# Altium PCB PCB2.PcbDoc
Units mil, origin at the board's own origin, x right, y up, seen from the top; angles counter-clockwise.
Board outline 1545.03 x 1900.03 mil, 2 copper layers (Top Layer, Bottom Layer); 45 components, 45 nets, 176 pads, 0 vias.
Unrouted connection lines stored in the file: 10.
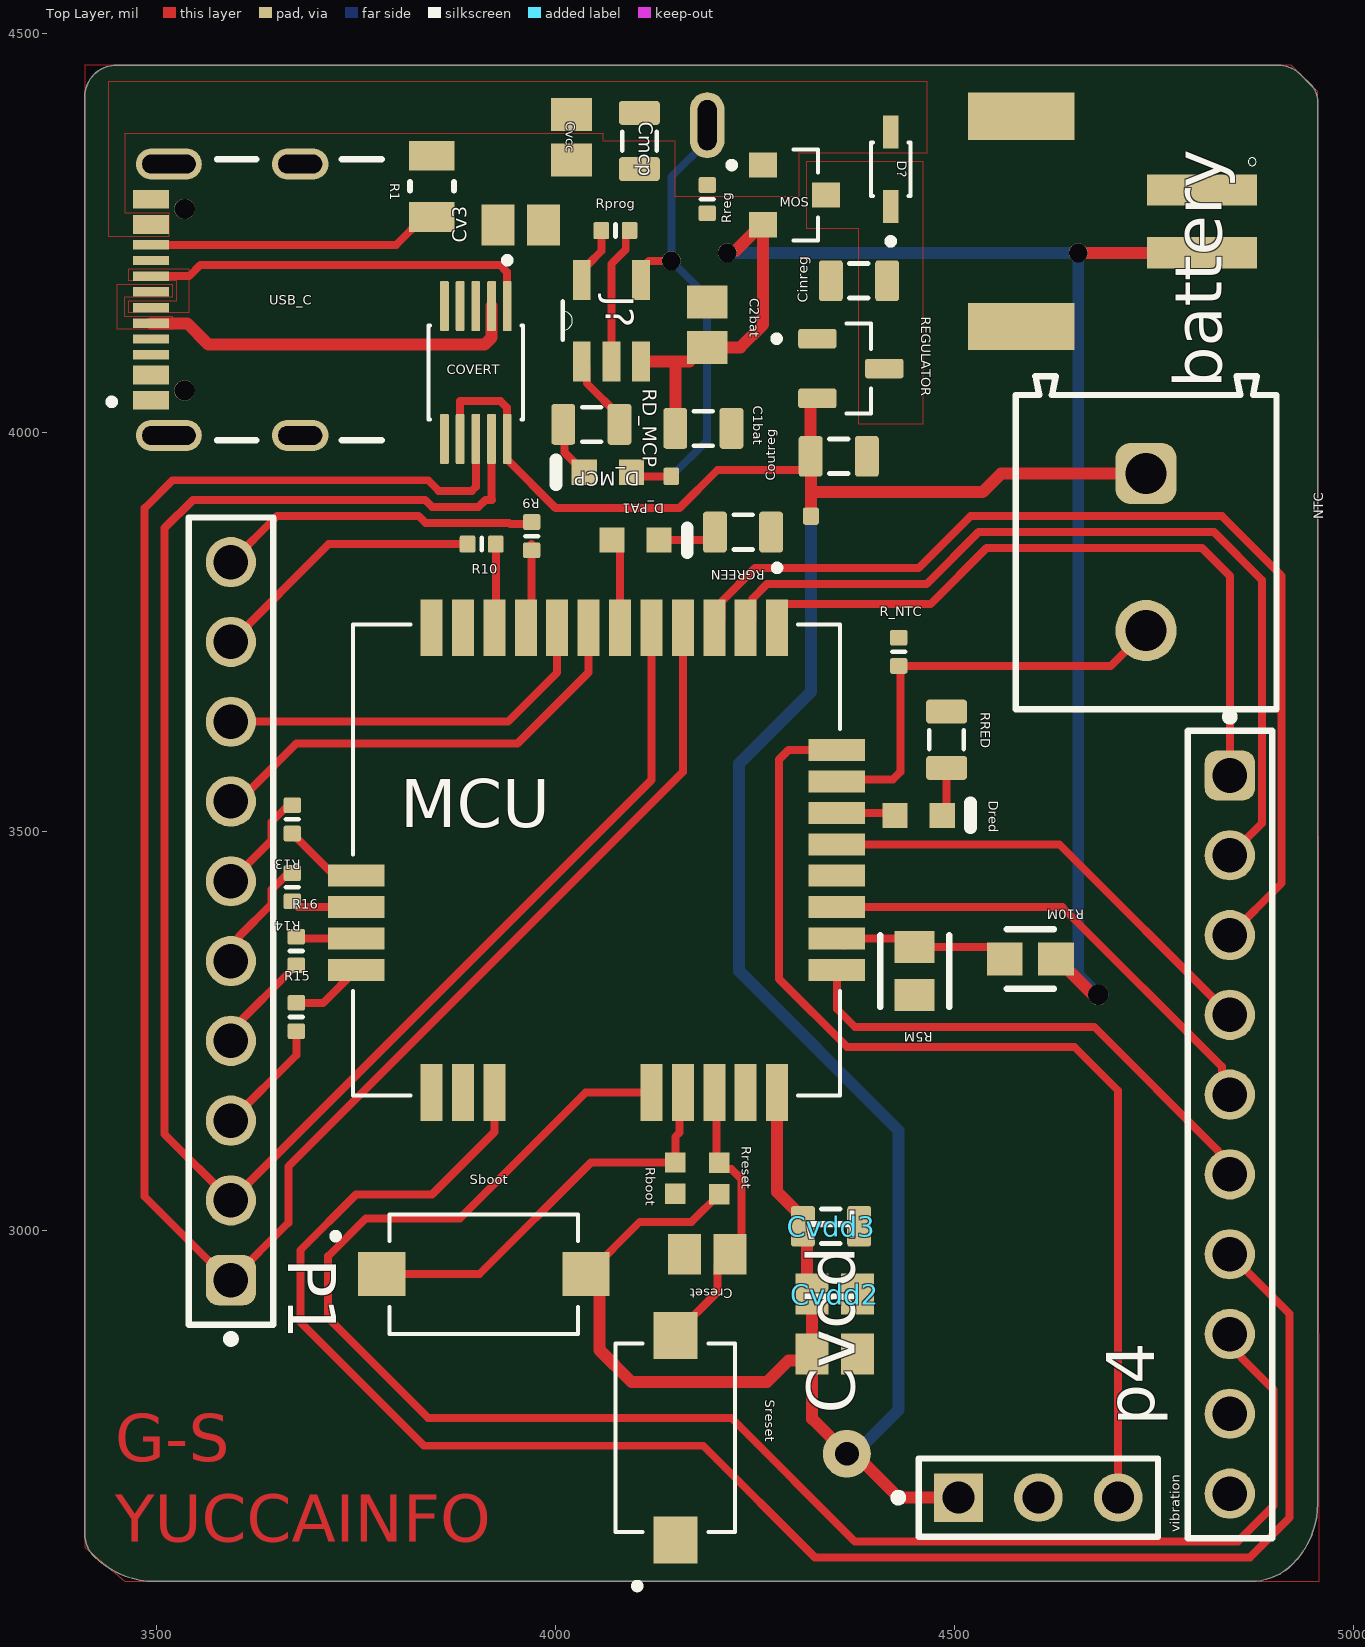
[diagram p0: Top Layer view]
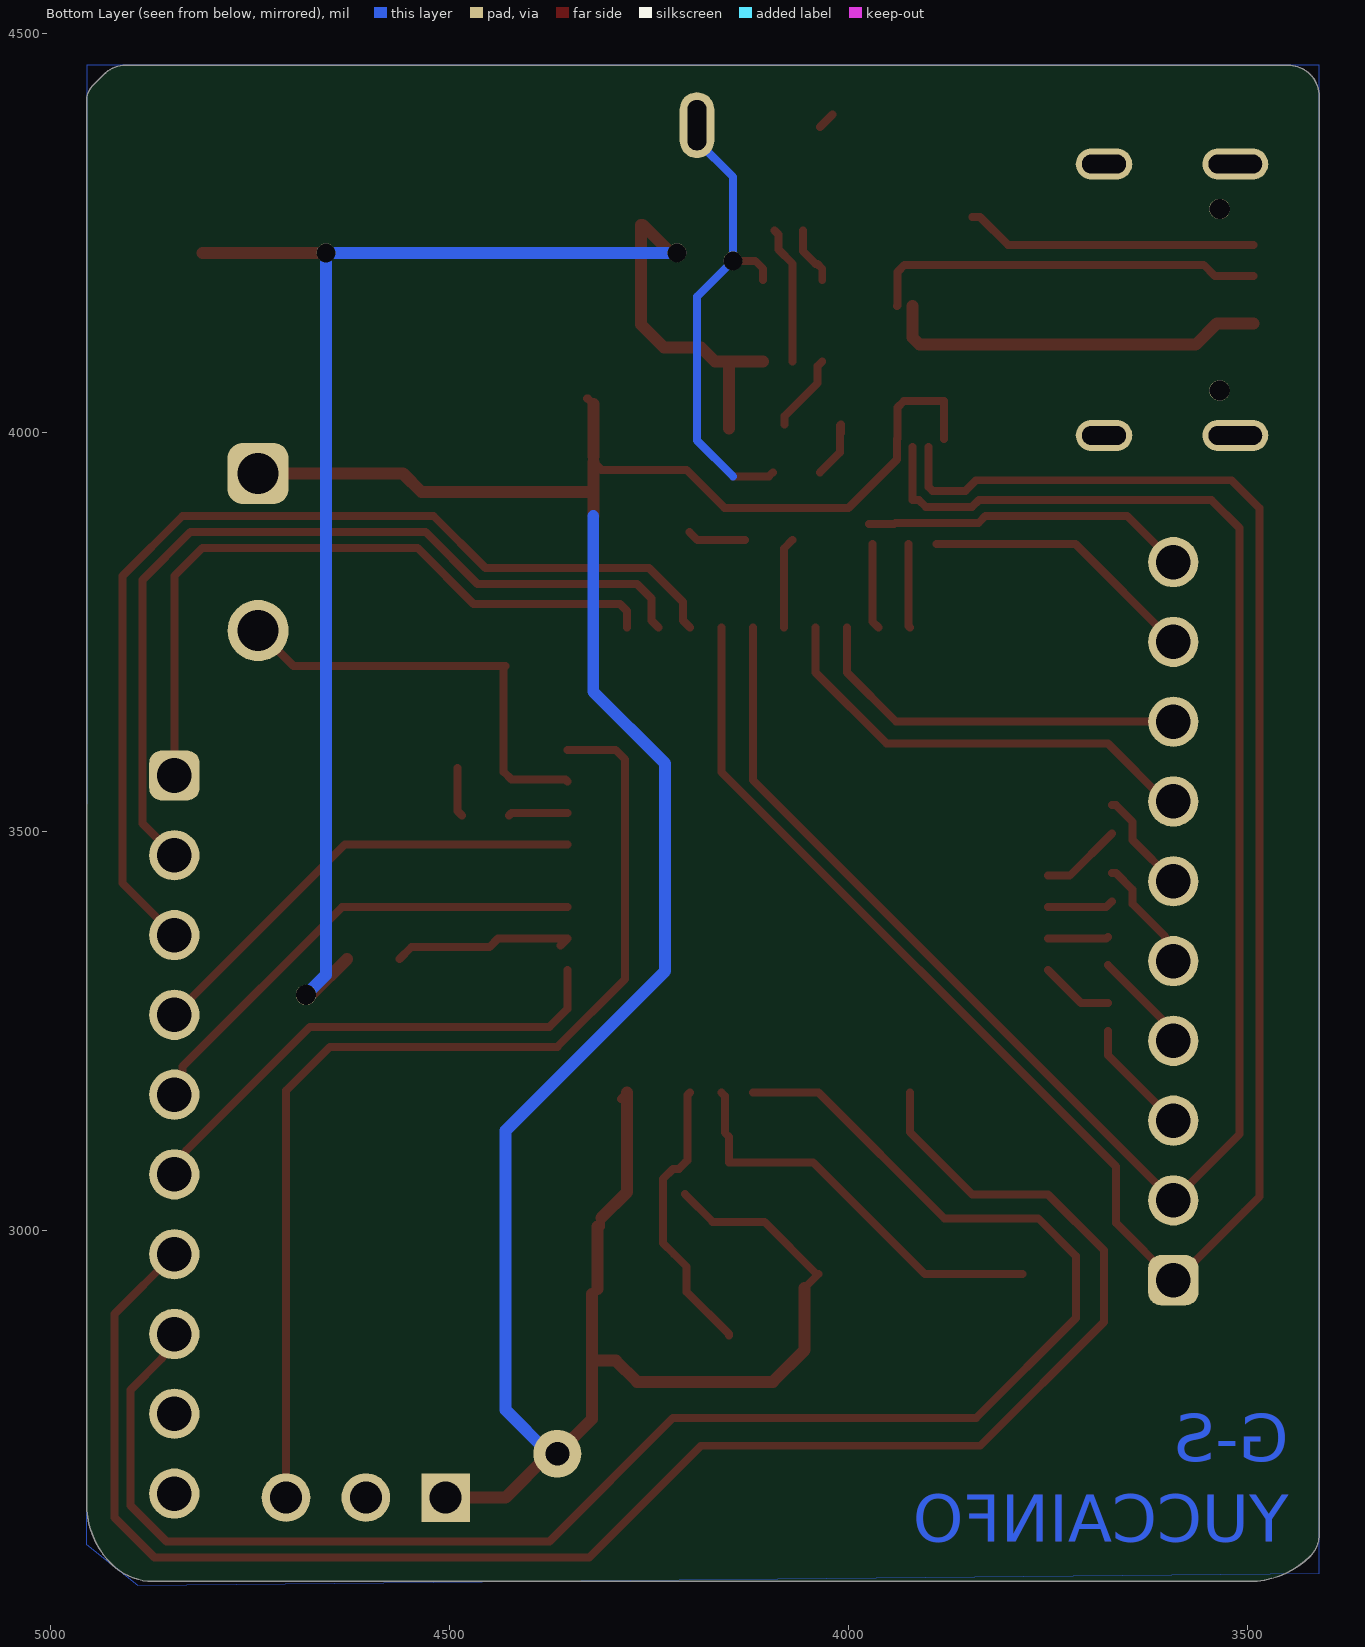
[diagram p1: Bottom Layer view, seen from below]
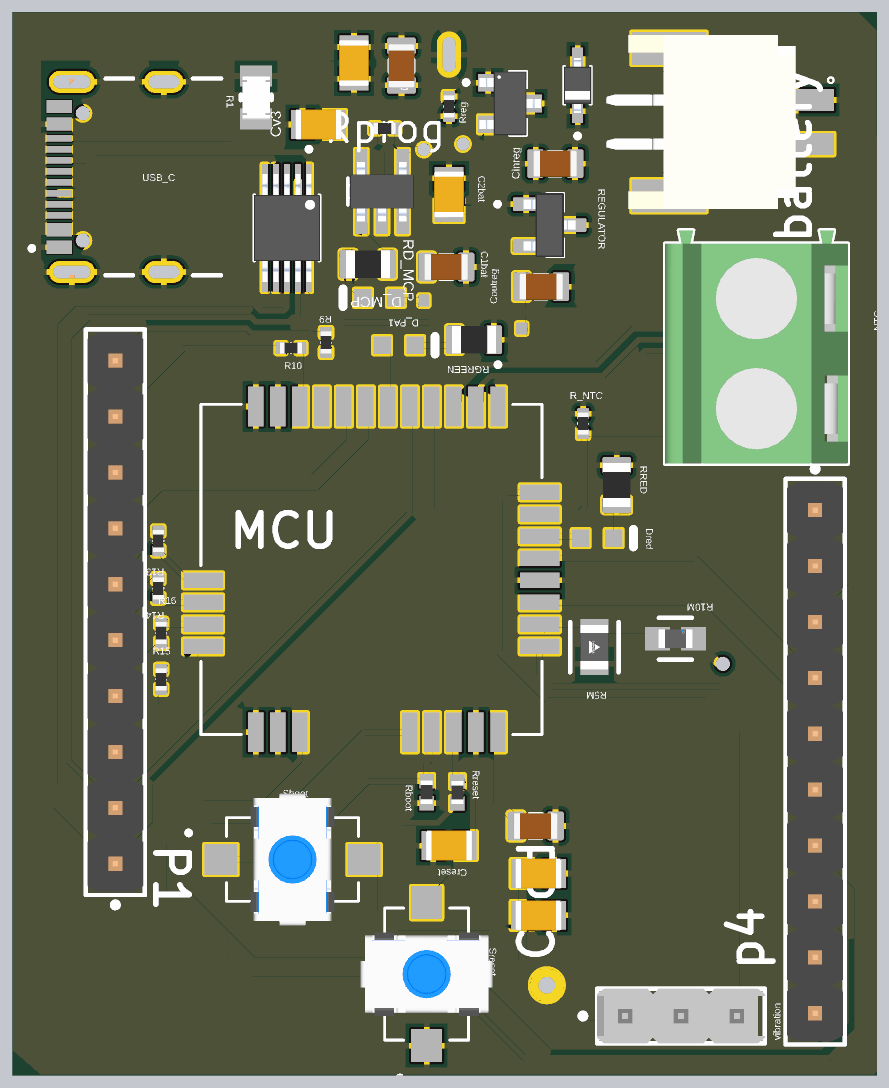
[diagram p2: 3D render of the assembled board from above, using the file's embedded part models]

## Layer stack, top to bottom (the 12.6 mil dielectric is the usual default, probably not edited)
Top Solder: solder mask 0.4, Solder Resist, Dk 3.5
Top Layer: signal copper 1.4
Dielectric 1: dielectric 12.6, FR-4, Dk 4.8
Bottom Layer: signal copper 1.4
Bottom Solder: solder mask 0.4, Solder Resist, Dk 3.5

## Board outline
3409.99,2619.14 3409.99,4420.86 cw(c3449.14,4420.86) 3421.45,4448.55 cw(c3449.14,4420.86) 3449.14,4460.02 4905.86,4460.02 cw(c4905.86,4420.86) 4933.55,4448.55 4946.48,4435.62 cw(c4925.86,4415) 4955.02,4415 4955.02,2657.43 cw(c4847.57,2657.43) 4923.55,2581.45 cw(c4871.72,2633.28) 4871.72,2559.99 3497.43,2559.99 cw(c3497.43,2667.43) 3421.45,2591.45 cw(c3449.14,2619.14)

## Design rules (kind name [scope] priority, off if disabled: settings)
Clearance [All] p1 off: gap=10 ignorepadtopadclearanceinfootprint=FALSE
DiffPairsRouting [All] p1: maxlimit=10 minlimit=10 mostfreqgap=10 toplayer_minwidth=15 toplayer_maxwidth=15 toplayer_prefwidth=15 bottomlayer_minwidth=15 bottomlayer_maxwidth=15 bottomlayer_prefwidth=15 maxuncoupledlength=500
PolygonConnect [All] p1: connectstyle=Relief reliefconductorwidth=10 reliefentries=4 polygonreliefangle="90 Angle" airgapwidth=10
RoutingVias [All] p1: holewidth=28 width=50 viastyle="Through Hole" minholewidth=28 minwidth=50 maxholewidth=28 maxwidth=50
SolderMaskExpansion [All] p1: expansion=4 istentingtop=FALSE
SupplyNets "Schematic Supply Nets_3" [InNet('GND')] p1: voltage=0.000
SupplyNets "Schematic Supply Nets_2" [InNet('Vbat')] p2: voltage=0.000
SupplyNets "Schematic Supply Nets_1" [InNet('VBUS')] p3: voltage=0.000
SupplyNets "Schematic Supply Nets" [InNet('3V3')] p4: voltage=0.000
Width [All] p1: maxlimit=10 minlimit=10 preferedwidth=10
29 further rules are at their usual default settings.

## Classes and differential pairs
differential pair D: +D_P -D_N

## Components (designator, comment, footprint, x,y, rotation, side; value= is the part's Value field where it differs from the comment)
battery "" JST_S2B-PH-SM4-TB 4810,4264.37 r90 top
C1bat "Capacitor 4.7µF +/-40% 25V 0805" CAPC0805(2012)145_L 4185,4005 r180 top value=4.7µF
C2bat "Capacitor 100 nF +/-10% 50 V 0805" CAPC2013X95X50LL10T25 4190,4135 r270 top value=100nF
Cinreg "Capacitor 10µF +/-20% 25V 0805" CAPC0805(2012)145_L 4380,4190 r180 top value=10µF
Cmcp "Capacitor 4.7µF +/-40% 25V 0805" CAPC0805(2012)145_L 4105,4365 r270 top value=4.7µF
Coutreg "Capacitor 10µF +/-20% 25V 0805" CAPC0805(2012)145_L 4355,3970 r0 top value=10µF
COVERT "COM-16278" SOP50P490X120-10N 3900,4075 r270 top
Creset "Capacitor 100 nF +/-10% 50 V 0805" CAPC2013X95X50LL10T25 4190,2970 r180 top value=100nF
Cv3 "Capacitor 100 nF +/-10% 50 V 0805" CAPC2013X95X50LL10T25 3956.46,4260 r180 top value=100nF
Cvcc "Capacitor 100 nF +/-10% 50 V 0805" CAPC2013X95X50LL10T25 4020,4370 r270 top value=100nF
Cvdd1 "Capacitor 100 nF +/-10% 50 V 0805" CAPC2013X95X50LL10T25 4350,2845 r180 top value=100nF
Cvdd2 "Capacitor 100 nF +/-10% 50 V 0805" CAPC2013X95X50LL10T25 4350,2920 r180 top value=100nF
Cvdd3 "Capacitor 10µF +/-20% 25V 0805" CAPC0805(2012)145_L 4345,3005 r180 top value=10µF
D? "B5819WS-TP" SOD2512X115N 4420,4330 r90 top
D_MCP "" LTST-C190GKT_V 4065.47,3950 r180 top
D_PA1 "" AVAG-HSMX-C190_V 4100,3865 r0 top
Dred "" AVAG-HSMX-C190_V 4455,3520 r0 top
J? "MCP73831T-2ACI/OT" SOT95P280X145-5N 4070,4140 r90 top
MCU "RAK3172" XCVR_RAK3172-8-SM-NI 4051.18,3464.06 r0 top
MOS "" TRANS_TSM500P02CX 4299.37,4297.6 r0 top
NTC "" 691213710002 4740,3850 r270 top
P1 "" 61301011121 3593.06,3387.44 r90 top
p4 "" 61301011121 4845,3120 r270 top
R1 "CRCW08055K10FKEA" FP-CRCW0805-e3-MFG 3845,4308.39 r270 top
R5M "" FP-WSLP0805-MFG 4450,3324.92 r90 top
R9 "Resistor 22R  +/-5 % 0402 63 mW" RESC0402(1005)_L 3970,3870 r90 top value=22
R10 "Resistor 22R  +/-5 % 0402 63 mW" RESC0402(1005)_L 3907.28,3860 r180 top value=22
R10M "" FP-CRCW0603-e3-IPC_A 4595,3340 r0 top
R13 "Resistor 22R  +/-5 % 0402 63 mW" RESC0402(1005)_L 3670,3515 r270 top value=22
R14 "Resistor 22R  +/-5 % 0402 63 mW" RESC0402(1005)_L 3670,3430 r270 top value=22
R15 "Resistor 22R  +/-5 % 0402 63 mW" RESC0402(1005)_L 3675,3267.28 r90 top value=22
R16 "Resistor 22R  +/-5 % 0402 63 mW" RESC0402(1005)_L 3675,3350 r90 top value=22
R_NTC "10KR2F" RESC0402(1005)_L 4430,3725 r270 top value=10k
Rboot "Resistor 10k +/-1% 0402 63 mW" RESC1005X40X25ML05T05 4150,3065.31 r90 top value=10k
RD_MCP "Resistor 470R +/-5% 0805 125 mW" RESC0805(2012)_L 4045,4010 r0 top value=470
REGULATOR "" SOT95P237X112-3N 4370,4080 r0 top
RGREEN "1KR5J" RESC0805(2012)_L 4235,3875 r0 top value=1k
Rprog "2KR2J" RESC0402(1005)_L 4075,4252.91 r0 top value=2k
RRED "1KR5J" RESC0805(2012)_L 4490,3615 r90 top value=1k
Rreg "10KR2F" RESC0402(1005)_L 4190,4292.28 r90 top value=10k
Rreset "Resistor 10k +/-1% 0402 63 mW" RESC1005X40X25ML05T05 4205,3065 r270 top value=10k
Sboot "" SW_TS10-63-26-BE-250-SMT-TR 3910,2945 r0 top
Sreset "" SW_TS10-63-26-BE-250-SMT-TR 4150,2740 r90 top
USB_C "USB4105-GF-A" GCT_USB4105-GF-A 3679.88,4166.22 r90 top
vibration "" MOLX-22-28-4033_V 4605,2665 r0 top

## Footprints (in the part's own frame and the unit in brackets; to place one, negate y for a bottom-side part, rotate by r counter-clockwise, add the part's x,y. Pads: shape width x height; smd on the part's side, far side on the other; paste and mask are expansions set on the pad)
61301011121 [mm] "Pin Header, pitch 2.54 mm, THT, Vertical, single row, 10p"
  rrect50% 1.6x1.6 hole 1.1: 1(-11.43,0)
  round 1.6 hole 1.1: 2(-8.89,0) 3(-6.35,0) 4(-3.81,0) 5(-1.27,0) 6(1.27,0) 7(3.81,0) 8(6.35,0) 9(8.89,0) 10(11.43,0)
  silkscreen extent -13.42,-1.35 12.85,1.35, body extent -12.7,-1.27 12.7,1.27, height 8.57
691213710002 [mm] "5,00mm - modular - green - Horizontal entry with rising cage clamp -  10,0mm height - 02p"
  rrect50% 1.95x1.95 hole 1.3: 1(-2.5,0)
  round 1.95 hole 1.3: 2(2.5,0)
  silkscreen extent -5.6,-4.15 5,4.15, body extent -5.6,-4.15 5,4.15, height 10.05
AVAG-HSMX-C190_V [mm] "SMD, 2-Leads, Body 1.6x0.8mm, Height 0.9mm"
  rect 0.8x0.8 smd: 1(-0.75,0) 2(0.75,0)
  silkscreen extent 1.65,-0.4 1.65,0.4, body extent -0.8,-0.4 0.8,0.4, height 0.9
CAPC0805(2012)145_L [mm] "Chip Capacitor, Body 2.0x1.2mm, Height 1.45mm, IPC High Density"
  rrect25% 0.76x1.3 smd: 1(-0.9,0) 2(0.89,0)
  silkscreen extent -0.3,-0.55 0.3,0.55, body extent -1,-0.6 1,0.6, height 1.45
CAPC2013X95X50LL10T25 [mm] "Chip Capacitor, 2-Leads, Body 2.10x1.35mm, IPC High Density"
  rect 1.05x1.3 smd: 1(-0.725,0) 2(0.725,0)
  body extent -1.05,-0.67 1.05,0.67, height 0.95
FP-CRCW0603-e3-IPC_A [mil]
  rect 44.69x41.82 smd paste+0 mask+0: 1(-32.1,0) 2(32.1,0)
  silkscreen extent -30,-37 30,37, body extent -74,-41 74,41, height 10
FP-CRCW0805-e3-MFG [mm]
  rect 0.95x1.45 smd paste+0 mask+0: 1(-0.975,0) 2(0.975,0)
  silkscreen extent -0.13,-0.7 0.13,0.7, body extent -1.55,-0.82 1.55,0.82, height 0.25
FP-WSLP0805-MFG [mm]
  rect 1.02x1.27 smd paste+0 mask+0: 1(-0.76,0) 2(0.76,0)
  silkscreen extent -1.14,-1.1 1.14,1.1, body extent -1.37,-0.86 1.37,0.86, height 0.25
GCT_USB4105-GF-A [mm]
  rect 0.6x1.15 smd mask+0.05: A1_B12(-3.2,4.755) A4_B9(-2.4,4.755) B1_A12(3.2,4.755) B4_A9(2.4,4.755)
  rect 0.3x1.15 smd mask+0.05: A5(-1.25,4.755) A6(-0.25,4.755) A7(0.25,4.755) A8(1.25,4.755) B5(1.75,4.755) B6(0.75,4.755) B7(-0.75,4.755) B8(-1.75,4.755)
  oval 1x2.1 hole 0.6 slot 1.7 at 90 deg: SH1(-4.32,4.18) SH2(4.32,4.18)
  oval 1x1.8 hole 0.6 slot 1.4 at 90 deg: SH3(-4.32,0) SH4(4.32,0)
  round 0.65 hole 0.65 unplated: ""(-2.89,3.68) ""(2.89,3.68)
  silkscreen extent -4.47,-2.6 4.47,6.1
JST_S2B-PH-SM4-TB [mm]
  rect 1x3.5 smd: 1(1,0) 2(-1,0)
  rect 1.5x3.4 smd: P1(3.35,5.75) P2(-3.35,5.75)
  silkscreen extent 1.77,-1.73 2.03,-1.47, body extent -3.95,0 3.95,8.6, height 5.5
LTST-C190GKT_V [mm] "SMD, 2-Leads, Body 1.6x0.8mm"
  rect 0.8x0.8 smd: 1(-0.75,0) 2(0.75,0)
  silkscreen extent 1.65,-0.4 1.65,0.4, body extent -0.8,-0.4 0.8,0.4, height 0.9
MOLX-22-28-4033_V [mm] "THD, 3-Leads, Body 7.62x2.49mm, Pitch 2.54mm"
  rect 1.55x1.55 hole 1.02: 1(-2.54,0)
  round 1.55 hole 1.02: 2(0,0) 3(2.54,0)
  silkscreen extent -4.58,-1.24 3.81,1.24, body extent -3.81,-1.24 3.81,1.24, height 8.38
RESC0402(1005)_L [mm] "Chip Resistor, Body 1.0x0.5mm, IPC High Density"
  rrect25% 0.5x0.55 smd: 1(-0.45,0) 2(0.45,0)
  silkscreen extent 0,-0.2 0,0.2, body extent -0.5,-0.25 0.5,0.25, height 0.3
RESC0805(2012)_L [mm] "Chip Resistor, Body 2.0x1.3mm, IPC High Density"
  rrect25% 0.76x1.3 smd: 1(-0.9,0) 2(0.89,0)
  silkscreen extent -0.3,-0.55 0.3,0.55, body extent -1,-0.62 1,0.63, height 0.6
RESC1005X40X25ML05T05 [mm] "Chip Resistor, 2-Leads, Body 1.05x0.55mm, IPC Low Density"
  rect 0.65x0.65 smd: 1(-0.5,0) 2(0.5,0)
  body extent -0.53,-0.28 0.53,0.28, height 0.4
SOD2512X115N [mm]
  rect 1.05x0.5 smd: A(1.185,0) C(-1.185,0)
  silkscreen extent -2.4,-0.63 0.85,0.63, body extent -1.25,-0.63 1.25,0.63, height 1.15
SOP50P490X120-10N [mm]
  rrect25% 1.59x0.28 smd: 1(-2.115,1) 2(-2.115,0.5) 3(-2.115,0) 4(-2.115,-0.5) 5(-2.115,-1) 6(2.115,-1) 7(2.115,-0.5) 8(2.115,0) 9(2.115,0.5) 10(2.115,1)
  silkscreen extent -3.68,-1.5 1.5,1.5, body extent -2.45,-1.5 2.45,1.5, height 1
SOT95P237X112-3N [mm]
  rrect25% 1.22x0.62 smd: 1(-1.065,0.95) 2(-1.065,-0.95) 3(1.065,0)
  silkscreen extent -2.46,-1.43 0.64,1.43, body extent -1.18,-1.45 1.18,1.45, height 1.12
SOT95P280X145-5N [mil]
  rect 50x22 smd: 1(-51,37) 2(-51,0) 3(-51,-37) 4(51,-37) 5(51,37)
  silkscreen extent -24,49 24,61, body extent -53,-57 53,57, height 57
SW_TS10-63-26-BE-250-SMT-TR [mm]
  rect 1.5x1.4 smd: 1(-3.25,0) 2(3.25,0)
  silkscreen extent -4.82,-1.9 3,1.9, body extent -1.9,-3.7 1.9,3.7, height 2.2
TRANS_TSM500P02CX [mm]
  rect 0.9x0.8 smd: 1(-1,0.95) 2(-1,-0.95) 3(1,0)
  silkscreen extent -2.1,-1.45 0.75,1.45, body extent -1.4,-1.45 1.4,1.45, height 1.2
XCVR_RAK3172-8-SM-NI [mm]
  rect 0.7x1.8 smd: 1(5.75,7.4) 2(4.75,7.4) 3(3.75,7.4) 4(2.75,7.4) 5(1.75,7.4) 6(0.75,7.4) 7(-0.25,7.4) 8(-1.25,7.4) 9(-2.25,7.4) 10(-3.25,7.4) 11(-4.25,7.4) 12(-5.25,7.4) 17(-5.25,-7.4) 18(-4.25,-7.4) 19(-3.25,-7.4) 20(1.75,-7.4) 21(2.75,-7.4) 22(3.75,-7.4) 23(4.75,-7.4) 24(5.75,-7.4)
  rect 1.8x0.7 smd: 13(-7.65,-0.5) 14(-7.65,-1.5) 15(-7.65,-2.5) 16(-7.65,-3.5) 25(7.65,-3.5) 26(7.65,-2.5) 27(7.65,-1.5) 28(7.65,-0.5) 29(7.65,0.5) 30(7.65,1.5) 31(7.65,2.5) 32(7.65,3.5)
  silkscreen extent -7.75,-7.5 7.75,9.4

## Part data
battery: library part S2B-PH-SM4-TB, "Connector Header Surface Mount, Right Angle 2 position 0.079 (2.00mm)", Package=None
C1bat Cmcp: library part CMP-001-00080-4, "Chip Capacitor, 4.7µF +/-40%, 25V, 0805, Thickness 1.45 mm", Case/Package=0805, Max Operating Temperature=85°C, Min Operating Temperature=-55°C, Tolerance=20%, Voltage Rating=25V
C2bat Creset Cv3 Cvcc Cvdd1 Cvdd2: library part CMP-001-00018-6, "Chip Capacitor, 100 nF, +/- 10%, 50 V, 0805 (2012 Metric)", Capacitor Type=Ceramic, Case/Package=0805, Max Operating Temperature=125°C, Min Operating Temperature=-55°C, Tolerance=10%, Voltage Rating=50V
Cinreg Coutreg Cvdd3: library part CMP-001-00079-4, "Chip Capacitor, 10µF +/-20%, 25V, 0805, Thickness 1.45 mm", Case/Package=0805, Max Operating Temperature=85°C, Min Operating Temperature=-55°C, Tolerance=10%, Voltage Rating=25V
COVERT: "SparkFun Accessories USB to Serial IC - CH340E (10 Pack)", Package=None
D?: "Diode Schottky 40 V 1A Surface Mount SOD-323", Package="SOD-323 Taiwan Semiconductor Corporation"
D_MCP: library part CMP-007-00022-2, "LED Uni-Color Green, 100 mW, 30 mA, -55 to 85 degC, 2-Pin SMD, RoHS, Tape and Reel", Case/Package=0603, Colour=Green, Forward Current=20mA, Forward Voltage=2.1V, Manufacturer=Lite-On, Max Operating Temperature=85°C, Min Operating Temperature=-55°C, Package Description="2-Pin Surface Mount Device, Body 1.6 x 0.8 mm", Package Quantity=3000, Package Reference=C190GKT, Power=100mW
D_PA1: library part CMP-007-00017-2, "LED Uni-Color Yellow, 65 mW, 20 mA, -40 to 85 degC, 2-Pin SMD, RoHS, Tape and Reel", Case/Package=0603, Colour=Yellow, Forward Current=20mA, Forward Voltage=2.1V, Manufacturer=Avago, Max Operating Temperature=85°C, Min Operating Temperature=-40°C, Package Description="2-Pin Surface Mount Device, Body 1.6 x 0.8 mm, Height 0.9 mm", Package Quantity=4000, Package Reference=HSMX-C190, Power=52mW
Dred: library part CMP-007-00014-2, "LED Uni-Color Red, 65 mW, 20 mA, -40 to 85 degC, 2-Pin SMD, RoHS, Tape and Reel", Case/Package=0603, Colour=Red, Forward Current=20mA, Forward Voltage=1.8V, Manufacturer=Avago, Max Operating Temperature=85°C, Min Operating Temperature=-40°C, Package Description="2-Pin Surface Mount Device, Body 1.6 x 0.8 mm, Height 0.9 mm", Package Quantity=4000, Package Reference=HSMX-C190, Power=78mW
J?: "Charger IC Lithium Ion/Polymer SOT-23-5", Package="SOT-23 Microchip"
MCU: library part RAK3172-8-SM-NI, "RF IC Transceiver LoRaWAN 864MHz, 865MHz, 868MHz 2V ~ 3.6V Supply, Without IPEX Connector", Package=None
MOS: library part TSM500P02CX, "P-Channel 20 V 4.7A (Tc) 1.56W (Tc) Surface Mount SOT-23", Package="SOT-23-3 Taiwan Semiconductor"
NTC: library part CMP-1502-02526-2, Color=Green, Current=10A, Max Operating Temperature=105°C, Min Operating Temperature=-40°C, Voltage=300V
P1 p4: library part CMP-1502-01082-5, Color=Black, Contact Resistance=20mΩ, Current Rating=3A, Flammability Rating="UL94 V-0", Insulation Resistance=1GΩ, Max Operating Temperature=105°C, Min Operating Temperature=-40°C, Operating Supply Voltage=250V
R1: library part CMP-2001-04024-2, "RES Thick Film, 5.1kΩ, 1%, 0.125W, 100ppm/°C, 0805", Case Code (Imperial)=0805, Case Code (Metric)=2012, Max Operating Temperature=155°C, Max Power Dissipation=125mW, Min Operating Temperature=-55°C, Package Quantity=10, Resistance=5.1kR, Temperature Coefficient=100ppm/°C, Tolerance=1%, Voltage Rating=150V
R5M: library part CMP-02407-013125-1, "RES 0.005 OHM 1% 1W 0805", Case Code (Imperial)=0805, Case Code (Metric)=2012, Max Operating Temperature=170°C, Max Power Dissipation=1W, Min Operating Temperature=-65°C, Resistance=5mR, Resistance Tolerance=1%, Resistor Type="Metal Strip", Temperature Coefficient=110ppm/°C
R9 R10 R13 R14 R15 R16: library part CMP-009-00164-3, "Chip Resistor, 22 Ohms, +/-5 %, 63 mW, -55 to 155 degC, 0402", Case/Package=0402, Max Operating Temperature=155°C, Min Operating Temperature=-55°C, Power=63mW, Tolerance=5%
R10M: library part CMP-2000-03844-2, "RES Thick Film, 10MΩ, 5%, 0.1W, 200ppm/°C, 0603", Case Code (Imperial)=0603, Case Code (Metric)=1608, Max Operating Temperature=155°C, Max Power Dissipation=100mW, Min Operating Temperature=-55°C, Package Quantity=1, Resistance=10MR, Temperature Coefficient=200ppm/°C, Tolerance=5%, Voltage Rating=75V
R_NTC Rreg: library part CMP-009-00066-2, "10K 0.063W 1% 0402 (1005 Metric)  SMD", Case/Package=0402, Power=63mW, Tolerance=1%
Rboot Rreset: library part CMP-009-00019-5, "Chip Resistor, 10 KOhm, +/- 1%, 63 mW, -55 to 155 degC, 0402 (1005 Metric)", Case/Package=0402, Max Operating Temperature=155°C, Min Operating Temperature=-55°C, Power=63mW, Tolerance=1%, Voltage Rating=50V
RD_MCP: library part CMP-009-00122-3, "Chip Resistor, 470 Ohms, +/-5%, 125 mW, -55 to 155 degC, 0805", Case/Package=0805, Max Operating Temperature=155°C, Min Operating Temperature=-55°C, Power=125mW, Tolerance=5%
REGULATOR: library part MCP1700T-3302E_TT, "Pwr Sply Func,Voltage Regulator,LDO,SOT-23,PD 369.6mW,VO 3.3V,Regline +/-0.75%/V", Package="SOT-23 Microchip"
RGREEN RRED: library part CMP-009-00076-2, "1K 0.125W 5% 0805 (2012 Metric)  SMD", Case/Package=0805, Power=125mW, Tolerance=5%
Rprog: library part CMP-009-00091-2, "2K 0.063W 5% 0402 (1005 Metric)  SMD", Case/Package=0402, Power=63mW, Tolerance=5%
Sboot Sreset: library part TS10-63-26-BE-250-SMT-TR, "6.1 x 3.8 mm, 2.6 mm Actuator Height, 250 gf, Surface Mount, SPST, Tactile Switch", Package=None
USB_C: Package=None
vibration: library part CMP-1676-00001-5, "Male Header, Pitch 2.54 mm, 1 x 3 Position, Height 8.38 mm, Tail Length 3.18 mm, RoHS, Bulk", Colour=Black, Current Rating="4 A", Manufacturer=Molex, Max Operating Temperature="75 degC", Min Operating Temperature="0 degC", Package Quantity=1, Voltage Rating="250 V"

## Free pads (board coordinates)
  rrect100% 43.31x82.68 hole 62.99 slot 23.62 at 0 deg paste-99999 mask+0: 4(4190,4385)
  rrect25% 19.68x21.65 smd: 5(4145,3945) 5(4320,3895)
  round 23.62 hole 23.62 unplated: 6(4145,4215) 9(4215,4225) 9(4655,4225)
  round 60 hole 30: 10(4365,2720)
  round 25.59 hole 25.59 unplated: 11(4680,3295)

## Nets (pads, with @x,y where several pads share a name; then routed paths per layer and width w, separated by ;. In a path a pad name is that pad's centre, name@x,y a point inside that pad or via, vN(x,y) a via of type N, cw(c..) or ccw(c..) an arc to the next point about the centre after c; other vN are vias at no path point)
3V3: Coutreg.1 COVERT.7 COVERT.10 Cv3.1 Cvdd1.2 Cvdd2.2 Cvdd3.2 MCU.24 NTC.1 pad.5@4320,3895 pad.10 REGULATOR.2 Rreset.2 Sboot.2 vibration.1 | length 3782.6
  Top Layer w10: COVERT.7 3880.32,4039.14 3930.86,4039.14 3938.86,4031.14 3938.86,3992.24 COVERT.10 3939.37,3965.94 4000,3905.32 4155.31,3905.32 4203.15,3953.15 4309.61,3953.15 Coutreg.1@4319.57,3963.11 ; Sboot.2@4055,2927.95 Sboot.2 4039.92,2945 4105.51,3010.59 4170.28,3010.59 Rreset.2 ; MCU.24 MCU.24@4285.43,3164.85 ; Cvdd3.2 Cvdd3.2@4309.96,3015.63 ; Cvdd1.2@4313.1,2836.65 Cvdd1.2 ; Cvdd2.2@4314.96,2926.5 Cvdd2.2 ; Coutreg.1 Coutreg.1@4319.57,3963.11 ; REGULATOR.2@4319.57,4035.39 4326.77,4042.6 REGULATOR.2 ; pad.5@4319.78,3895.22 pad.5@4320,3895 ; 4319.78,3925.22 4320,3925 ; Coutreg.1@4319.78,3962.89 Coutreg.1@4319.57,3963.11
  Top Layer w15: Sboot.2@4055,2927.95 4055,2850 4095,2810 4265,2810 4291.65,2836.65 Cvdd1.2@4313.1,2836.65 ; MCU.24 4277.56,3048.03 Cvdd3.2@4309.96,3015.63 ; Cvdd2.2@4314.96,2926.5 Cvdd3.2@4314.96,3005 ; Coutreg.1 REGULATOR.2@4319.57,4035.39 ; pad.5@4319.78,3895.22 4319.78,3925.22 Coutreg.1@4319.78,3962.89 ; 4320,3925 4535,3925 4558.43,3948.43 NTC.1 ; Cvdd2.2 Cvdd1.2 4321.46,2763.78 pad.10@4365,2720.24 ; pad.10 4375,2720 4430,2665 vibration.1
  Bottom Layer w10: pad.10 pad.10@4375,2720
  Bottom Layer w15: 4320,3895 4320,3675 4230,3585 4230,3325 4430,3125 4430,2775 pad.10@4375,2720
BOOT0: MCU.21 Rboot.2 Sboot.1 | length 517.6
  Top Layer w10: Sboot.1 3904.39,2945 4044.39,3085 Rboot.2 4150,3117.2 4155.08,3122.28 4155.08,3168.35 MCU.21
D_N: COVERT.2 USB_C.A7 USB_C.B7 | length 481.2
  Top Layer w15: USB_C.B7 3538.31,4136.69 3565,4110 3910.9,4110 3919.68,4118.79 COVERT.2
D_P: COVERT.1 USB_C.A6 USB_C.B6 | length 498.8
  Top Layer w10: USB_C.B6 3540.75,4195.75 3555,4210 3930,4210 3938.86,4201.14 3938.86,4158.78 COVERT.1
GND: battery.1 C1bat.1 C2bat.1 Cinreg.2 Cmcp.2 Coutreg.2 COVERT.3 Creset.2 Cv3.2 Cvcc.2 Cvdd1.1 Cvdd2.1 Cvdd3.1 MCU.11 MCU.12 MCU.17 MCU.18 MCU.23 MCU.28 p4.9 p4.10 pad.11 R1.1 R5M.1 R_NTC.1 Rboot.1 REGULATOR.1 RGREEN.2 RRED.2 Rreg.1 Sreset.1 USB_C.A1_B12 USB_C.B1_A12 USB_C.SH1 USB_C.SH2 USB_C.SH3 USB_C.SH4 vibration.2
I2C_SCL: P1.10 R9.2 | length 409.5
  Top Layer w10: P1.10 3651.06,3895.43 3828.24,3895.43 3836.94,3886.73 3941.4,3886.73 3943.13,3885 R9.2@3974.19,3885
I2C_SDA: P1.9 R10.2 | length 347.3
  Top Layer w10: P1.9 3715.63,3860 R10.2
LEV_BAT: MCU.26 R5M.2 R10M.1 | length 233.6
  Top Layer w10: MCU.26@4361.14,3356.85 MCU.26 4439.21,3365.63 R5M.2 4548.06,3354.84 R10M.1
NetCinreg_1: Cinreg.1 D?.C MOS.3 REGULATOR.3
NetD_MCP_2: D_MCP.2 RD_MCP.1 | length 81.6
  Top Layer w10: RD_MCP.1@4009.57,3999.37 RD_MCP.1 4011.05,4008.51 4011.05,3974.89 D_MCP.2
NetD_PA1_2: D_PA1.2 RGREEN.1 | length 74.2
  Top Layer w10: D_PA1.2 4189.57,3865 RGREEN.1
NetDred_2: Dred.2 RRED.1 | length 61.8
  Top Layer w10: Dred.2 4490,3525.47 RRED.1
NetJ?_1: J?.1 RD_MCP.2 | length 98.5
  Top Layer w10: J?.1 4039,4083 4039,4061.67 4080.04,4020.63 RD_MCP.2
NetJ?_2: J?.2 Rprog.2 | length 173.3
  Top Layer w10: J?.2 4070,4211.21 4087.87,4229.09 4087.87,4248.07 Rprog.2
NetJ?_5: J?.5 Rprog.1 | length 73.3
  Top Layer w10: J?.5 4033,4205 4039,4211 4041.2,4211 4057.28,4227.09 Rprog.1
NetMCU_9: MCU.9 R9.1 | length 107.7
  Top Layer w10: MCU.9 3970,3762.8 R9.1@3970,3860
NetMCU_10: MCU.10 R10.1 | length 105.3
  Top Layer w10: MCU.10 3925,3757.17 R10.1
NetMCU_13: MCU.13 R13.2 | length 101.9
  Top Layer w10: R13.2 3722.91,3444.37 MCU.13
NetMCU_14: MCU.14 R14.2 | length 83
  Top Layer w10: R14.2 3677.28,3405 MCU.14
NetMCU_15: MCU.15 R16.2 | length 75.9
  Top Layer w10: R16.2 3677.09,3365.63 MCU.15
NetMCU_16: MCU.16 R15.2 | length 92.1
  Top Layer w10: R15.2 3708.74,3285 MCU.16
NetR1_2: R1.2 USB_C.B5 | length 366.8
  Top Layer w10: USB_C.B5 3800.28,4235.12 3835.16,4270 R1.2
NTC: MCU.31 NTC.2 R_NTC.2 | length 546.9
  Top Layer w10: MCU.31 4354.76,3564.88 4422.6,3564.88 4432.28,3574.57 4432.28,3705 R_NTC.2 4695.71,3707.28 NTC.2
PA0_IO: MCU.29 p4.4 | length 581.2
  Top Layer w10: MCU.29 4631.26,3483.74 p4.4
PA1_IO: D_PA1.1 MCU.6 | length 113.8
  Top Layer w10: D_PA1.1 4080.71,3854.77 MCU.6
PA2_RX: MCU.2 p4.2 | length 1099.1
  Top Layer w10: MCU.2 4246.97,3764.17 4246.97,3791.97 4265,3810 4465,3810 4530,3875 4825,3875 4885,3815 4885,3510 p4.2
PA3_TX: MCU.1 p4.1 | length 885.4
  Top Layer w10: MCU.1 4277.56,3776.22 4286.34,3785 4470,3785 4540,3855 4810,3855 4845,3820 p4.1
PA8_IO: MCU.19 p4.7 | length 2188.1
  Top Layer w10: MCU.19 3923.23,3123.23 3845,3045 3750,3045 3680,2975 3680,2885 3835,2730 4185,2730 4325,2590 4870,2590 4920,2640 4920,2895 p4.7
PA9_IO: MCU.20 p4.8 | length 2125
  Top Layer w10: MCU.20 4037.72,3172.72 3880,3015 3762.43,3015 3715,2967.57 3715,2890 3840,2765 4220,2765 4375,2610 4855,2610 4900,2655 4900,2800 4860.38,2839.62 4860.38,2840.28 4845,2855.66 p4.8
PA10_IO: MCU.25 p4.6 | length 636.1
  Top Layer w10: MCU.25 4352.36,3277.64 4375,3255 4675,3255 4829.62,3100.38 4829.62,3099.72 4845,3084.34 p4.6
PA15_IO: MCU.3 p4.3 | length 1290.7
  Top Layer w10: MCU.3 4207.6,3764.17 4207.6,3787.6 4250,3830 4455,3830 4520,3895 4835,3895 4910,3820 4910,3435 p4.3
PB5_IO: Dred.1 MCU.30 | length 74.4
  Top Layer w10: MCU.30 4422.37,3523.11 Dred.1
PB12_IO: MCU.27 p4.5 | length 604.6
  Top Layer w10: MCU.27 4635,3405 4834.86,3205.14 4834.86,3180.14 p4.5
RESET: Creset.1 MCU.22 Rreset.1 Sreset.2 | length 357.5
  Top Layer w10: Sreset.2 4150,2869.92 4202.87,2922.8 4202.87,2954.33 Creset.1 4232.8,2984.25 4232.8,3064.32 4220.23,3076.89 4212.8,3076.89 Rreset.1 4201.91,3087.78 4201.91,3169.63 MCU.22
RX: COVERT.9 MCU.5 P1.2 | length 2311.5
  Top Layer w10: COVERT.9@3919.68,3981.73 3919.68,3915.75 3920,3915.43 3911.99,3915.43 3903.28,3906.73 3845.23,3906.73 3836.53,3915.43 3545.43,3915.43 3510,3880 3510,3120.5 P1.2 4120.08,3564.45 MCU.5
SPI_CLK: P1.4 R16.1 | length 128.8
  Top Layer w10: P1.4 3593.06,3250.35 R16.1
SPI_CS: P1.3 R15.1 | length 146.1
  Top Layer w10: P1.3 3675,3219.37 R15.1
SPI_MISO: P1.5 R14.1 | length 145.1
  Top Layer w10: P1.5 3603.2,3347.58 3603.2,3368.2 3644.17,3409.17 3644.17,3426.9 3664.99,3447.72 R14.1
SPI_MOSI: P1.6 R13.1 | length 130.1
  Top Layer w10: P1.6 3593.06,3438.06 3644.17,3489.17 3644.17,3511.9 3664.99,3532.72 R13.1
SWCLK: MCU.7 P1.7 | length 571.5
  Top Layer w10: P1.7 3602.44,3537.44 3675,3610 3952.23,3610 4041.34,3699.11 MCU.7
SWDIO: MCU.8 P1.8 | length 490.7
  Top Layer w10: P1.8 3940.29,3637.44 4001.97,3699.11 MCU.8
TX: COVERT.8 MCU.4 P1.1 | length 2553.4
  Top Layer w10: P1.1@3591.69,2935.46 3503.8,3023.35 3485.06,3042.1 3485.06,3079.69 3485,3079.74 3485,3905 3520,3940 3840.24,3940 3853.51,3926.73 3895,3926.73 3900,3931.73 COVERT.8@3900,3981.73 ; P1.1 3665,3009.37 3665,3080 4159.45,3574.45 MCU.4
Vbat: battery.2 C1bat.2 C2bat.2 J?.3 MOS.2 pad.9 R10M.2 | length 2049.4
  Top Layer w10: pad.9@4215,4225 4217.61,4227.61 pad.9@4225.44,4227.61 ; MOS.2@4258.03,4260.2 MOS.2 ; R10M.2 R10M.2@4628.54,3340 ; 4673.54,3295 4680,3295
  Top Layer w15: J?.3 4167.62,4089 4185.08,4106.46 C2bat.2 4231.46,4106.46 4260,4135 MOS.2 ; C1bat.2 4149.96,4084.96 4154,4089 ; pad.9@4225.44,4227.61 MOS.2@4258.03,4260.2 ; R10M.2@4628.54,3340 4673.54,3295 ; pad.9@4655,4225 battery.2
  Bottom Layer w15: pad.9@4215,4225 4655,4225 4655,3320 4680,3295
VBUS: Cmcp.1 Cvcc.1 D?.A D_MCP.1 J?.4 MOS.1 pad.4 pad.5@4145,3945 pad.6 Rreg.2 USB_C.A4_B9 USB_C.B4_A9 | length 626.3
  Top Layer w10: Cvcc.1 Cvcc.1@4035.67,4382.87 ; D_MCP.1 4100,3945 pad.5@4145,3945 ; J?.4 4107,4205 4117,4215 pad.6
  Bottom Layer w10: 4145,3945 4190,3990 4190,4170 pad.6 4145,4320.31 4190,4365.31 pad.4
VIB: MCU.32 vibration.3 | length 1345.3
  Top Layer w10: MCU.32 4291.85,3601.85 4280,3590 4280,3315 4365,3230 4650,3230 4705,3175 vibration.3
pads on no net: battery.P1 battery.P2 COVERT.4 COVERT.5 COVERT.6 USB_C. USB_C.A5 USB_C.A8 USB_C.B8

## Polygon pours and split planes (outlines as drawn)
GND on Top Layer "NONET_L-01_P-001" (solid, shelved, pour order 12): 4955,4427.09 4922.08,4460.01 3409.99,4459.89 3409.93,2602.98 3460,2559.99 4957.23,2560.27
VBUS on Top Layer "NONET_L-01_P-001" (solid, shelved, pour order 10): 3515,4245 3440,4245 3440,4440 3915,4440 4465,4440 4465,4435 4465,4430 4465,4350 4305,4350 4305,4295 4150,4295 4150,4365 4060,4365 4060,4375 4059.23,4374.23 3460.77,4374.23 3460,4375 3460,4275 3515,4275
D_P on Top Layer "NONET_L-01_P-001" (solid, shelved, pour order 9): 3465,4205 3540,4205 3540,4150 3465,4150 3465,4165 3525,4165 3525,4190 3465,4190
D_N on Top Layer "NONET_L-01_P-001" (solid, shelved, pour order 8): 3520,4185 3450,4185 3450,4130 3520,4130 3520,4145 3460,4145 3460,4170 3520,4170
NetCinreg_1 on Top Layer "NONET_L-01_P-001" (solid, shelved, pour order 6): 4315,4340 4460,4340 4460,4010 4380,4010 4380,4255 4315,4255
GND on Bottom Layer "NONET_L-01_P-001" (solid, shelved, pour order 13): 3409.99,4460.02 4955.02,4460.02 4955.39,2606.34 4890.68,2555.22 3409.99,2570

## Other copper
Top Layer:
  text "G-S / YUCCAINFO" at 3448.37,2590.16 h100.85
Bottom Layer:
  text "G-S / YUCCAINFO" at 3448.37,2590.16 h100.85

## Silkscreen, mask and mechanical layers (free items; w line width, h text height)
Mechanical 1:
  lines w10: 3459.57,4455 4905,4455 4905.86,4455 cw(c4905.86,4420.86) 4930,4445 4936.46,4438.54 4942.93,4432.07 cw(c4925.86,4415) 4950,4415 4950,2657.43 cw(c4847.57,2657.43) 4920,2585 cw(c4871.72,2633.28) 4871.72,2565 3497.43,2565 cw(c3497.43,2667.43) 3425,2595 cw(c3449.14,2619.14) 3415,2619.14 3415,4420.86 cw(c3449.14,4420.86) 3425,4445 cw(c3449.14,4420.86) 3449.14,4455 3470,4455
